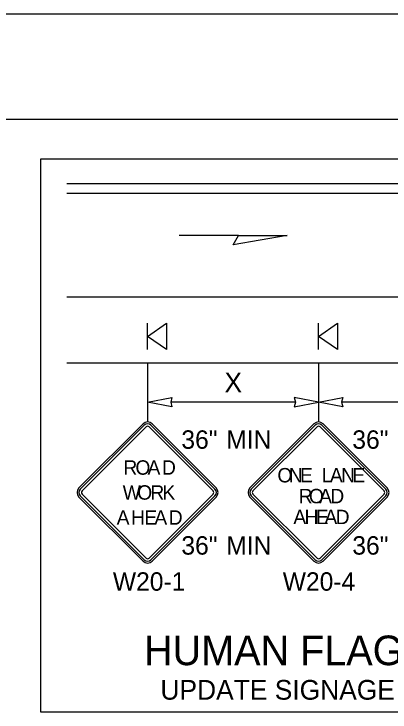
# Model space of a CAD drawing. Extents: x 99999.1 to 100095.7, y 99995 to 100010.7.
# Drawn here: x 100045 to 100046.43, y 100003.48 to 100006.132 of the extents above; entities that cross this region are included whole.
import ezdxf

# ---------------------------------------------------------------- set-up
doc = ezdxf.new("R2010")
doc.units = 0
for name, color, linetype in [('RD_ED_ShoulderPavedEdge', 7, 'Continuous'), ('RD_MK_LineDblYellowCenter', 7, 'Continuous'), ('RD_MK_LineEdgeWhite', 7, 'Continuous'), ('SH_DE_DetailHeading2Text', 7, 'Continuous'), ('TR_SN_ConstructionSigns', 7, 'Continuous'), ('TR_WZ_PortableSignMountBlk-Org', 7, 'Continuous'), ('TR_WZ_WorkZoneDetails', 7, 'Continuous'), ('TR_WZ_WorkZoneTextCurrent', 7, 'Continuous')]:
    doc.layers.add(name, color=color, linetype=linetype)

msp = doc.modelspace()

# ---------------------------------------------------------------- linework, layer by layer
at = {"layer": 'RD_ED_ShoulderPavedEdge'}
for p, q in [((100040.1076, 100005.7323), (100055.6424, 100005.7323)), ((100045.2015, 100004.8073), (100048.9925, 100004.8073))]:
    msp.add_line(p, q, dxfattribs=at)
at = {"layer": 'RD_MK_LineDblYellowCenter'}
for p, q in [((100045.2015, 100005.4886), (100048.0081, 100005.4886)), ((100045.2015, 100005.4511), (100048.0081, 100005.4511))]:
    msp.add_line(p, q, dxfattribs=at)
at = {"layer": 'RD_MK_LineEdgeWhite'}
for p, q in [((100040.1076, 100006.1323), (100055.6424, 100006.1323)), ((100045.2015, 100005.0573), (100048.9925, 100005.0573))]:
    msp.add_line(p, q, dxfattribs=at)
at = {"layer": 'TR_SN_ConstructionSigns'}
for p, q in [((100045.4907, 100004.5751), (100045.2471, 100004.3315)), ((100045.4955, 100004.5703), (100045.2519, 100004.3267)), ((100045.2587, 100004.3199), (100045.5023, 100004.5635)), ((100045.5139, 100004.5635), (100045.7575, 100004.3199)), ((100045.7643, 100004.3267), (100045.5207, 100004.5703)), ((100045.7691, 100004.3315), (100045.5255, 100004.5751)), ((100046.1407, 100004.5751), (100045.8971, 100004.3315)), ((100046.1455, 100004.5703), (100045.9019, 100004.3267)), ((100045.9087, 100004.3199), (100046.1523, 100004.5635)), ((100046.1639, 100004.5635), (100046.4075, 100004.3199)), ((100046.4143, 100004.3267), (100046.1707, 100004.5703)), ((100046.4191, 100004.3315), (100046.1755, 100004.5751)), ((100045.2471, 100004.2967), (100045.4907, 100004.0531)), ((100045.2519, 100004.3015), (100045.4955, 100004.0579)), ((100045.5023, 100004.0647), (100045.2587, 100004.3083)), ((100045.7575, 100004.3083), (100045.5139, 100004.0647)), ((100045.5207, 100004.0579), (100045.7643, 100004.3015)), ((100045.5255, 100004.0531), (100045.7691, 100004.2967)), ((100045.8971, 100004.2967), (100046.1407, 100004.0531)), ((100045.9019, 100004.3015), (100046.1455, 100004.0579)), ((100046.1523, 100004.0647), (100045.9087, 100004.3083)), ((100046.4075, 100004.3083), (100046.1639, 100004.0647)), ((100046.1707, 100004.0579), (100046.4143, 100004.3015)), ((100046.1755, 100004.0531), (100046.4191, 100004.2967))]:
    msp.add_line(p, q, dxfattribs=at)
for centre, radius, start, end in [((100045.5081, 100004.5577), 0.0246, 45, 135), ((100046.1581, 100004.5577), 0.0246, 45, 135), ((100045.5081, 100004.5577), 0.0178, 45, 135), ((100045.5081, 100004.5577), 0.0082, 45, 135), ((100046.1581, 100004.5577), 0.0178, 45, 135), ((100046.1581, 100004.5577), 0.0082, 45, 135), ((100045.2645, 100004.3141), 0.0246, 135, 225), ((100045.2645, 100004.3141), 0.0178, 135, 225), ((100045.2645, 100004.3141), 0.0082, 135, 225), ((100045.7517, 100004.3141), 0.0082, 315, 45), ((100045.7517, 100004.3141), 0.0178, 315, 45), ((100045.7517, 100004.3141), 0.0246, 315, 45), ((100045.9145, 100004.3141), 0.0246, 135, 225), ((100045.9145, 100004.3141), 0.0178, 135, 225), ((100045.9145, 100004.3141), 0.0082, 135, 225), ((100046.4017, 100004.3141), 0.0082, 315, 45), ((100046.4017, 100004.3141), 0.0178, 315, 45), ((100046.4017, 100004.3141), 0.0246, 315, 45), ((100045.5081, 100004.0705), 0.0246, 225, 315), ((100045.5081, 100004.0705), 0.0178, 225, 315), ((100045.5081, 100004.0705), 0.0082, 225, 315), ((100046.1581, 100004.0705), 0.0246, 225, 315), ((100046.1581, 100004.0705), 0.0178, 225, 315), ((100046.1581, 100004.0705), 0.0082, 225, 315)]:
    msp.add_arc(centre, radius, start, end, dxfattribs=at)
at = {"layer": 'TR_WZ_PortableSignMountBlk-Org'}
for p, q in [((100045.5081, 100004.8574), (100045.5081, 100004.9574)), ((100046.1581, 100004.8574), (100046.1581, 100004.9574))]:
    msp.add_line(p, q, dxfattribs=at)
for points in [[(100045.5081, 100004.9073), (100045.5799, 100004.9574), (100045.5799, 100004.8574)], [(100046.1581, 100004.9073), (100046.2299, 100004.9574), (100046.2299, 100004.8574)]]:
    msp.add_lwpolyline(points, close=True, dxfattribs=at)
at = {"layer": 'TR_WZ_WorkZoneDetails'}
for p, q in [((100045.854, 100005.291), (100045.6279, 100005.291)), ((100045.5081, 100004.8073), (100045.5081, 100004.5823)), ((100046.1581, 100004.8073), (100046.1581, 100004.5823)), ((100046.0702, 100004.6573), (100045.596, 100004.6573)), ((100046.7202, 100004.6573), (100046.246, 100004.6573))]:
    msp.add_line(p, q, dxfattribs=at)
for points in [[(100046.0382, 100005.291), (100045.8331, 100005.2549), (100045.854, 100005.291)], [(100045.5081, 100004.6573), (100045.6002, 100004.6754), (100045.596, 100004.6573), (100045.6002, 100004.6393)], [(100046.1581, 100004.6573), (100046.0659, 100004.6754), (100046.0702, 100004.6573), (100046.0659, 100004.6393)], [(100046.1581, 100004.6573), (100046.2502, 100004.6754), (100046.246, 100004.6573), (100046.2502, 100004.6393)]]:
    msp.add_lwpolyline(points, close=True, dxfattribs=at)
at = {"layer": 'TR_WZ_WorkZoneTextCurrent'}
msp.add_lwpolyline([(100045.1015, 100005.5823), (100049.1102, 100005.5823), (100049.1102, 100003.4799), (100045.1015, 100003.4799)], close=True, dxfattribs=at)

# ---------------------------------------------------------------- texts
at = {"layer": 'SH_DE_DetailHeading2Text'}
msp.add_text('HUMAN FLAGGER SUBSTITUTION', height=0.1125, rotation=360, dxfattribs=at).set_placement((100045.4946, 100003.658))
at = {"layer": 'TR_SN_ConstructionSigns'}
for s, p in [('36"', (100045.6365, 100004.4802)), ('MIN', (100045.8071, 100004.4802)), ('36"', (100046.2865, 100004.4802)), ('36"', (100045.6365, 100004.078)), ('MIN', (100045.8071, 100004.078)), ('36"', (100046.2865, 100004.078)), ('W20-1', (100045.376, 100003.9409)), ('W20-4', (100046.022, 100003.9409))]:
    msp.add_text(s, height=0.07, rotation=360, dxfattribs=at).set_placement(p)
for s, p in [('R', (100045.4161, 100004.3817)), ('O', (100045.4618, 100004.3817)), ('A', (100045.5079, 100004.3817)), ('D', (100045.5628, 100004.3817)), ('O', (100046.0017, 100004.3524)), ('N', (100046.0449, 100004.3524)), ('E', (100046.0875, 100004.3524)), ('L', (100046.1701, 100004.3524)), ('A', (100046.2013, 100004.3524)), ('N', (100046.2439, 100004.3524)), ('E', (100046.2866, 100004.3524)), ('W', (100045.4133, 100004.2868)), ('O', (100045.4686, 100004.2868)), ('R', (100045.5187, 100004.2868)), ('K', (100045.5646, 100004.2868)), ('R', (100046.0826, 100004.2731)), ('O', (100046.1214, 100004.2731)), ('A', (100046.1603, 100004.2731)), ('D', (100046.2029, 100004.2731)), ('A', (100045.3905, 100004.1918)), ('H', (100045.4452, 100004.1918)), ('E', (100045.4955, 100004.1918)), ('A', (100045.5338, 100004.1918)), ('D', (100045.5885, 100004.1918)), ('A', (100046.0624, 100004.1938)), ('H', (100046.105, 100004.1938)), ('E', (100046.1477, 100004.1938)), ('A', (100046.1805, 100004.1938)), ('D', (100046.2232, 100004.1938))]:
    msp.add_text(s, height=0.0547, dxfattribs=at).set_placement(p)
at = {"layer": 'TR_WZ_WorkZoneTextCurrent'}
msp.add_text('X', height=0.075, rotation=360, dxfattribs=at).set_placement((100045.8005, 100004.6948))
msp.add_text('UPDATE SIGNAGE & USE STOP/SLOW PADDLE', height=0.075, dxfattribs=at).set_placement((100045.5568, 100003.5268))

doc.saveas('drawing.dxf')
